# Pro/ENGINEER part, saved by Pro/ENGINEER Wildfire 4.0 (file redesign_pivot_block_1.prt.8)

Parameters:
  METRIC = "NO"

Other parameters: PITCH, DRILL_POINT_ANGLE, DRILL_DEPTH, DRILL_DIAMETER, THREAD_DIAMETER, THREADS_PER_INCH, THREAD_DEPTH, THREAD_LENGTH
